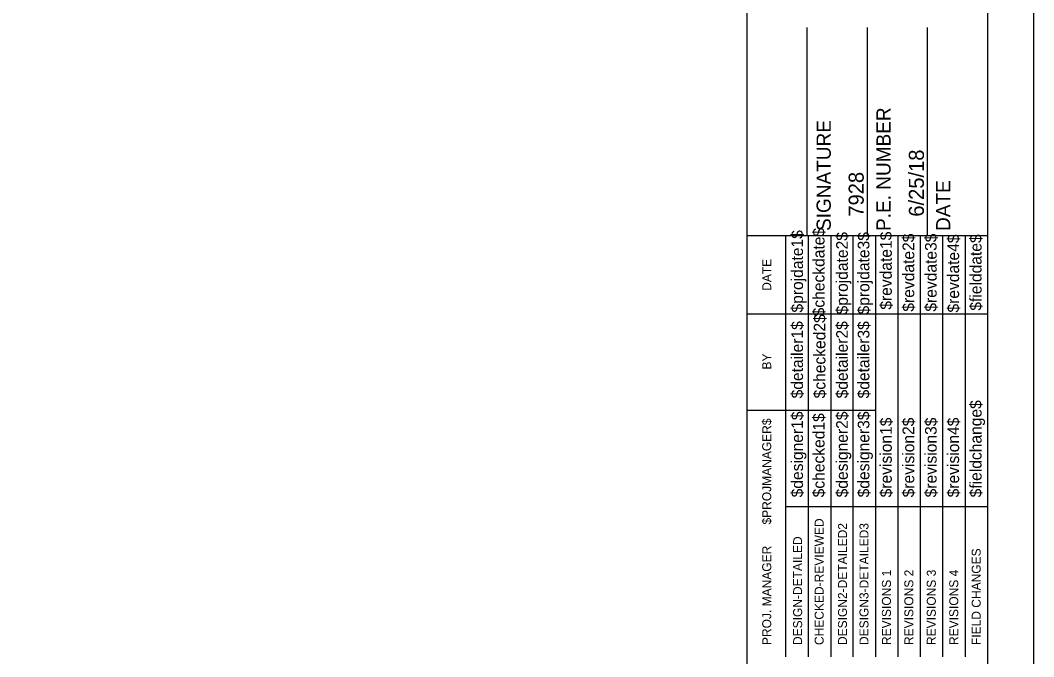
# Model space of a CAD drawing. Extents: x 916060 to 916918, y 329833 to 330383.
# Drawn here: x 916699.6 to 916910, y 330073.2 to 330205.4 of the extents above; entities that cross this region are included whole.
import ezdxf

# ---------------------------------------------------------------- set-up
doc = ezdxf.new("R2010")
doc.units = 0
doc.layers.add('Border', color=7, linetype='Continuous')
doc.layers.add('PLOT BOUNDARY', color=7, linetype='Continuous')

msp = doc.modelspace()

# ---------------------------------------------------------------- linework, layer by layer
at = {"layer": 'Border'}
for p, q in [((916850.49, 329848.18), (916850.49, 330373.18)), ((916900.49, 329848.18), (916900.49, 330373.18)), ((916862.99, 330160.68), (916862.99, 330203.92)), ((916875.49, 330160.68), (916875.49, 330203.92)), ((916887.99, 330160.68), (916887.99, 330203.92)), ((916850.49, 330160.68), (916900.49, 330160.68))]:
    msp.add_line(p, q, dxfattribs=at)
for points in [[(916858.57, 330144.43), (916858.57, 330160.68)], [(916863.23, 330073.2), (916863.23, 330160.68)], [(916867.89, 330160.68), (916867.89, 330073.2)], [(916872.55, 330073.2), (916872.55, 330160.68)], [(916877.21, 330073.2), (916877.21, 330160.68)], [(916881.86, 330073.2), (916881.86, 330160.68)], [(916886.52, 330073.2), (916886.52, 330160.68)], [(916891.18, 330073.2), (916891.18, 330160.68)], [(916895.84, 330073.2), (916895.84, 330160.68)], [(916858.57, 330073.2), (916858.57, 330157.15)], [(916850.49, 330144.43), (916900.49, 330144.43)], [(916850.49, 330124.43), (916858.57, 330124.43)], [(916858.57, 330124.43), (916877.2, 330124.43)], [(916858.57, 330104.43), (916900.49, 330104.43)]]:
    msp.add_lwpolyline(points, dxfattribs=at)
at = {"layer": 'PLOT BOUNDARY'}
msp.add_lwpolyline([(916060.03, 329832.87), (916910.03, 329832.87), (916910.03, 330382.87), (916060.03, 330382.87)], close=True, dxfattribs=at)

# ---------------------------------------------------------------- texts
at = {"layer": 'Border'}
for s, height, p in [('P.E. NUMBER', 2.9528, (916880.3, 330161.64)), ('SIGNATURE', 2.953, (916867.89, 330161.64)), ('6/25/18', 3.125, (916887.22, 330164.61)), ('7928', 3.125, (916874.72, 330164.61)), ('DATE', 2.953, (916892.7, 330161.64)), ('$projdate1$', 2.4227, (916862.11, 330144.69)), ('$checkdate$', 2.4227, (916866.58, 330143.9)), ('$projdate2$', 2.4227, (916871.42, 330144.29)), ('$projdate3$', 2.4227, (916875.9, 330144.29)), ('$revdate1$', 2.423, (916880.55, 330145.28)), ('$revdate2$', 2.423, (916885.21, 330144.88)), ('$revdate3$', 2.423, (916889.87, 330144.88)), ('$revdate4$', 2.423, (916894.53, 330144.69)), ('$fielddate$', 2.4227, (916899.19, 330145.08)), ('DATE', 1.857, (916855.51, 330149.21)), ('$checked2$', 2.423, (916866.77, 330126.86)), ('$detailer1$', 2.4227, (916862.11, 330126.86)), ('$detailer2$', 2.4227, (916871.42, 330126.86)), ('$detailer3$', 2.4227, (916875.9, 330126.86)), ('BY', 1.857, (916855.51, 330132.86)), ('$fieldchange$', 2.4227, (916899.19, 330106.3)), ('$designer1$', 2.4227, (916862.11, 330106.3)), ('$checked1$', 2.423, (916866.58, 330106.3)), ('$designer2$', 2.4227, (916871.42, 330106.3)), ('$designer3$', 2.4227, (916875.9, 330106.3)), ('$PROJMANAGER$', 1.8637, (916855.51, 330100.66)), ('$revision1$', 2.4227, (916880.55, 330106.3)), ('$revision2$', 2.4227, (916885.21, 330106.3)), ('$revision3$', 2.4227, (916889.87, 330106.3)), ('$revision4$', 2.4227, (916894.53, 330106.3)), ('CHECKED-REVIEWED', 1.8637, (916866.4, 330075.62)), ('DESIGN2-DETAILED2', 1.8637, (916871.24, 330075.62)), ('DESIGN3-DETAILED3', 1.8637, (916875.71, 330075.62)), ('DESIGN-DETAILED', 1.8637, (916861.93, 330075.62)), ('PROJ. MANAGER', 1.8637, (916855.51, 330075.62)), ('FIELD CHANGES', 1.8637, (916899.01, 330075.62)), ('REVISIONS 1', 1.8637, (916880.37, 330075.62)), ('REVISIONS 2', 1.8637, (916885.03, 330075.62)), ('REVISIONS 3', 1.8637, (916889.69, 330075.62)), ('REVISIONS 4', 1.8637, (916894.35, 330075.62))]:
    msp.add_text(s, height=height, rotation=90, dxfattribs=at).set_placement(p)

doc.saveas('drawing.dxf')
